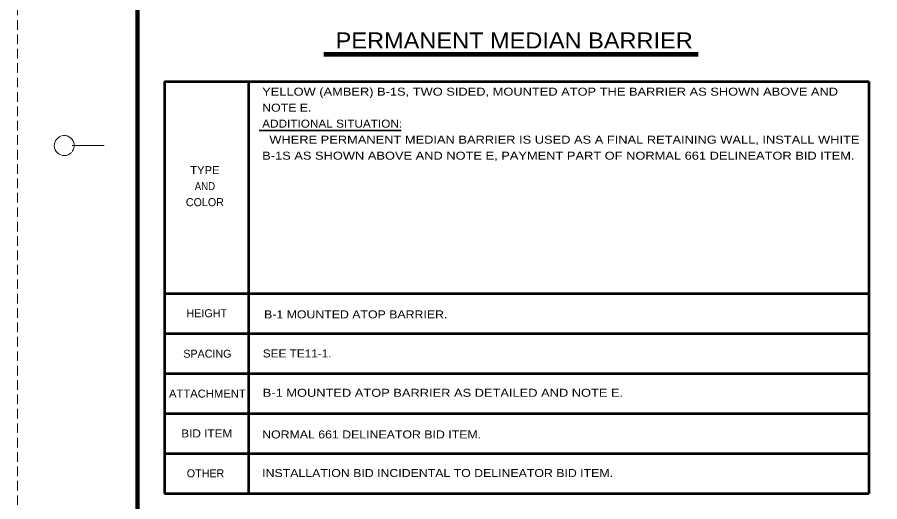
# Model space of a CAD drawing. Extents: x -60 to 620, y -42 to 398.
# Drawn here: x -60.3 to 155.3, y 155.5 to 276.6 of the extents above; entities that cross this region are included whole.
import ezdxf
from ezdxf.enums import TextEntityAlignment as Align

# ---------------------------------------------------------------- set-up
doc = ezdxf.new("R2010")
doc.units = 0
doc.header["$LTSCALE"] = 0.8
doc.linetypes.add('MEDIUM_DASHED', pattern=[4.5, 3, -1.5])
doc.layers.add('1', color=7, linetype='Continuous', lineweight=35)
doc.layers.add('61', color=7, linetype='Continuous', lineweight=35)

msp = doc.modelspace()

# ---------------------------------------------------------------- linework, layer by layer
at = {"layer": '1', "linetype": 'MEDIUM_DASHED', "lineweight": 13}
msp.add_line((-60.2155, 398.2688), (-60.2755, -41.7713), dxfattribs=at)
at = {"layer": '1', "lineweight": 53}
for p, q in [((16.3329, 267.6088), (109.8552, 267.6088)), ((16.3329, 267.1088), (109.8552, 267.1088)), ((-23.4869, 260.5388), (152.5131, 260.5388)), ((-23.4869, 260.5388), (-23.4869, 157.5388)), ((-2.4869, 260.5388), (-2.4869, 157.5388)), ((152.5131, 260.5388), (152.5131, 157.5388)), ((-23.4869, 207.5388), (152.5131, 207.5388)), ((-23.4869, 197.5388), (152.5131, 197.5388)), ((-23.4869, 187.5388), (152.5131, 187.5388)), ((-23.4869, 177.5388), (152.5131, 177.5388)), ((-23.4869, 167.5388), (152.5131, 167.5388)), ((-23.4869, 157.5388), (152.5131, 157.5388))]:
    msp.add_line(p, q, dxfattribs=at)
at = {"layer": '1'}
msp.add_line((0.1595, 248.251), (35.6937, 248.251), dxfattribs=at)
at = {"layer": '61', "lineweight": 13}
msp.add_line((-46.5155, 244.5087), (-38.5155, 244.5087), dxfattribs=at)
at = {"layer": '61', "lineweight": 158}
msp.add_lwpolyline([(608.8245, 388.2688), (-30.2155, 388.2688), (-30.2155, -31.7512)], dxfattribs=at)
at = {"layer": '61', "lineweight": 13}
msp.add_arc((-48.5177, 244.51), 2.5, 323.13009, 315.37577, dxfattribs=at)

# ---------------------------------------------------------------- texts
at = {"layer": '1'}
for s, height, width, p in [('PERMANENT MEDIAN BARRIER', 4, 1.1, (19.2931, 268.7933)), ('YELLOW (AMBER) B-1S, TWO SIDED, MOUNTED ATOP THE BARRIER AS SHOWN ABOVE AND', 2, 1.2, (0.9372, 256.9841)), ('NOTE E.', 2, 1.15, (0.9372, 252.9841)), ('ADDITIONAL SITUATION:', 2, 1.1, (0.9372, 248.9841)), ('  WHERE PERMANENT MEDIAN BARRIER IS USED AS A FINAL RETAINING WALL, INSTALL WHITE', 2, 1.2, (0.9372, 244.9841)), ('B-1S AS SHOWN ABOVE AND NOTE E, PAYMENT PART OF NORMAL 661 DELINEATOR BID ITEM.', 2, 1.2, (0.9372, 240.9841)), ('B-1 MOUNTED ATOP BARRIER.', 2, 1.15, (1.4081, 201.3111)), ('SEE TE11-1.', 2, 1.1, (1.0934, 191.5433)), ('B-1 MOUNTED ATOP BARRIER AS DETAILED AND NOTE E.', 2, 1.2, (1.0804, 181.7086)), ('NORMAL 661 DELINEATOR BID ITEM.', 2, 1.15, (0.9377, 171.3017)), ('INSTALLATION BID INCIDENTAL TO DELINEATOR BID ITEM.', 2, 1.15, (0.9377, 161.6481))]:
    msp.add_text(s, height=height, dxfattribs=dict(at, width=width)).set_placement(p)
for s, width, p in [('TYPE', 1.05, (-13.3824, 237.3621)), ('AND', 0.9, (-13.3824, 233.3621)), ('ATTACHMENT', 1.05, (-12.7599, 181.5125)), ('BID ITEM', 1.1, (-12.9155, 171.5474))]:
    msp.add_text(s, height=2, dxfattribs=dict(at, width=width)).set_placement(p, align=Align.CENTER)
for s, p in [('COLOR', (-13.3825, 229.3621)), ('HEIGHT', (-12.9155, 201.5984)), ('SPACING', (-12.7598, 191.4776)), ('OTHER', (-13.2268, 161.5822))]:
    msp.add_text(s, height=2, dxfattribs=at).set_placement(p, align=Align.CENTER)

doc.saveas('drawing.dxf')
